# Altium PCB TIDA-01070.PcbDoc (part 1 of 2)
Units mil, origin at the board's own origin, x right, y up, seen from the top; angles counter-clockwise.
Board outline 4200 x 3450 mil, 4 copper layers (Top Layer, Signal Layer 1, Signal Layer 2, Bottom Layer), stack 61.668 mil thick; 155 components, 69 nets, 375 pads, 212 vias.
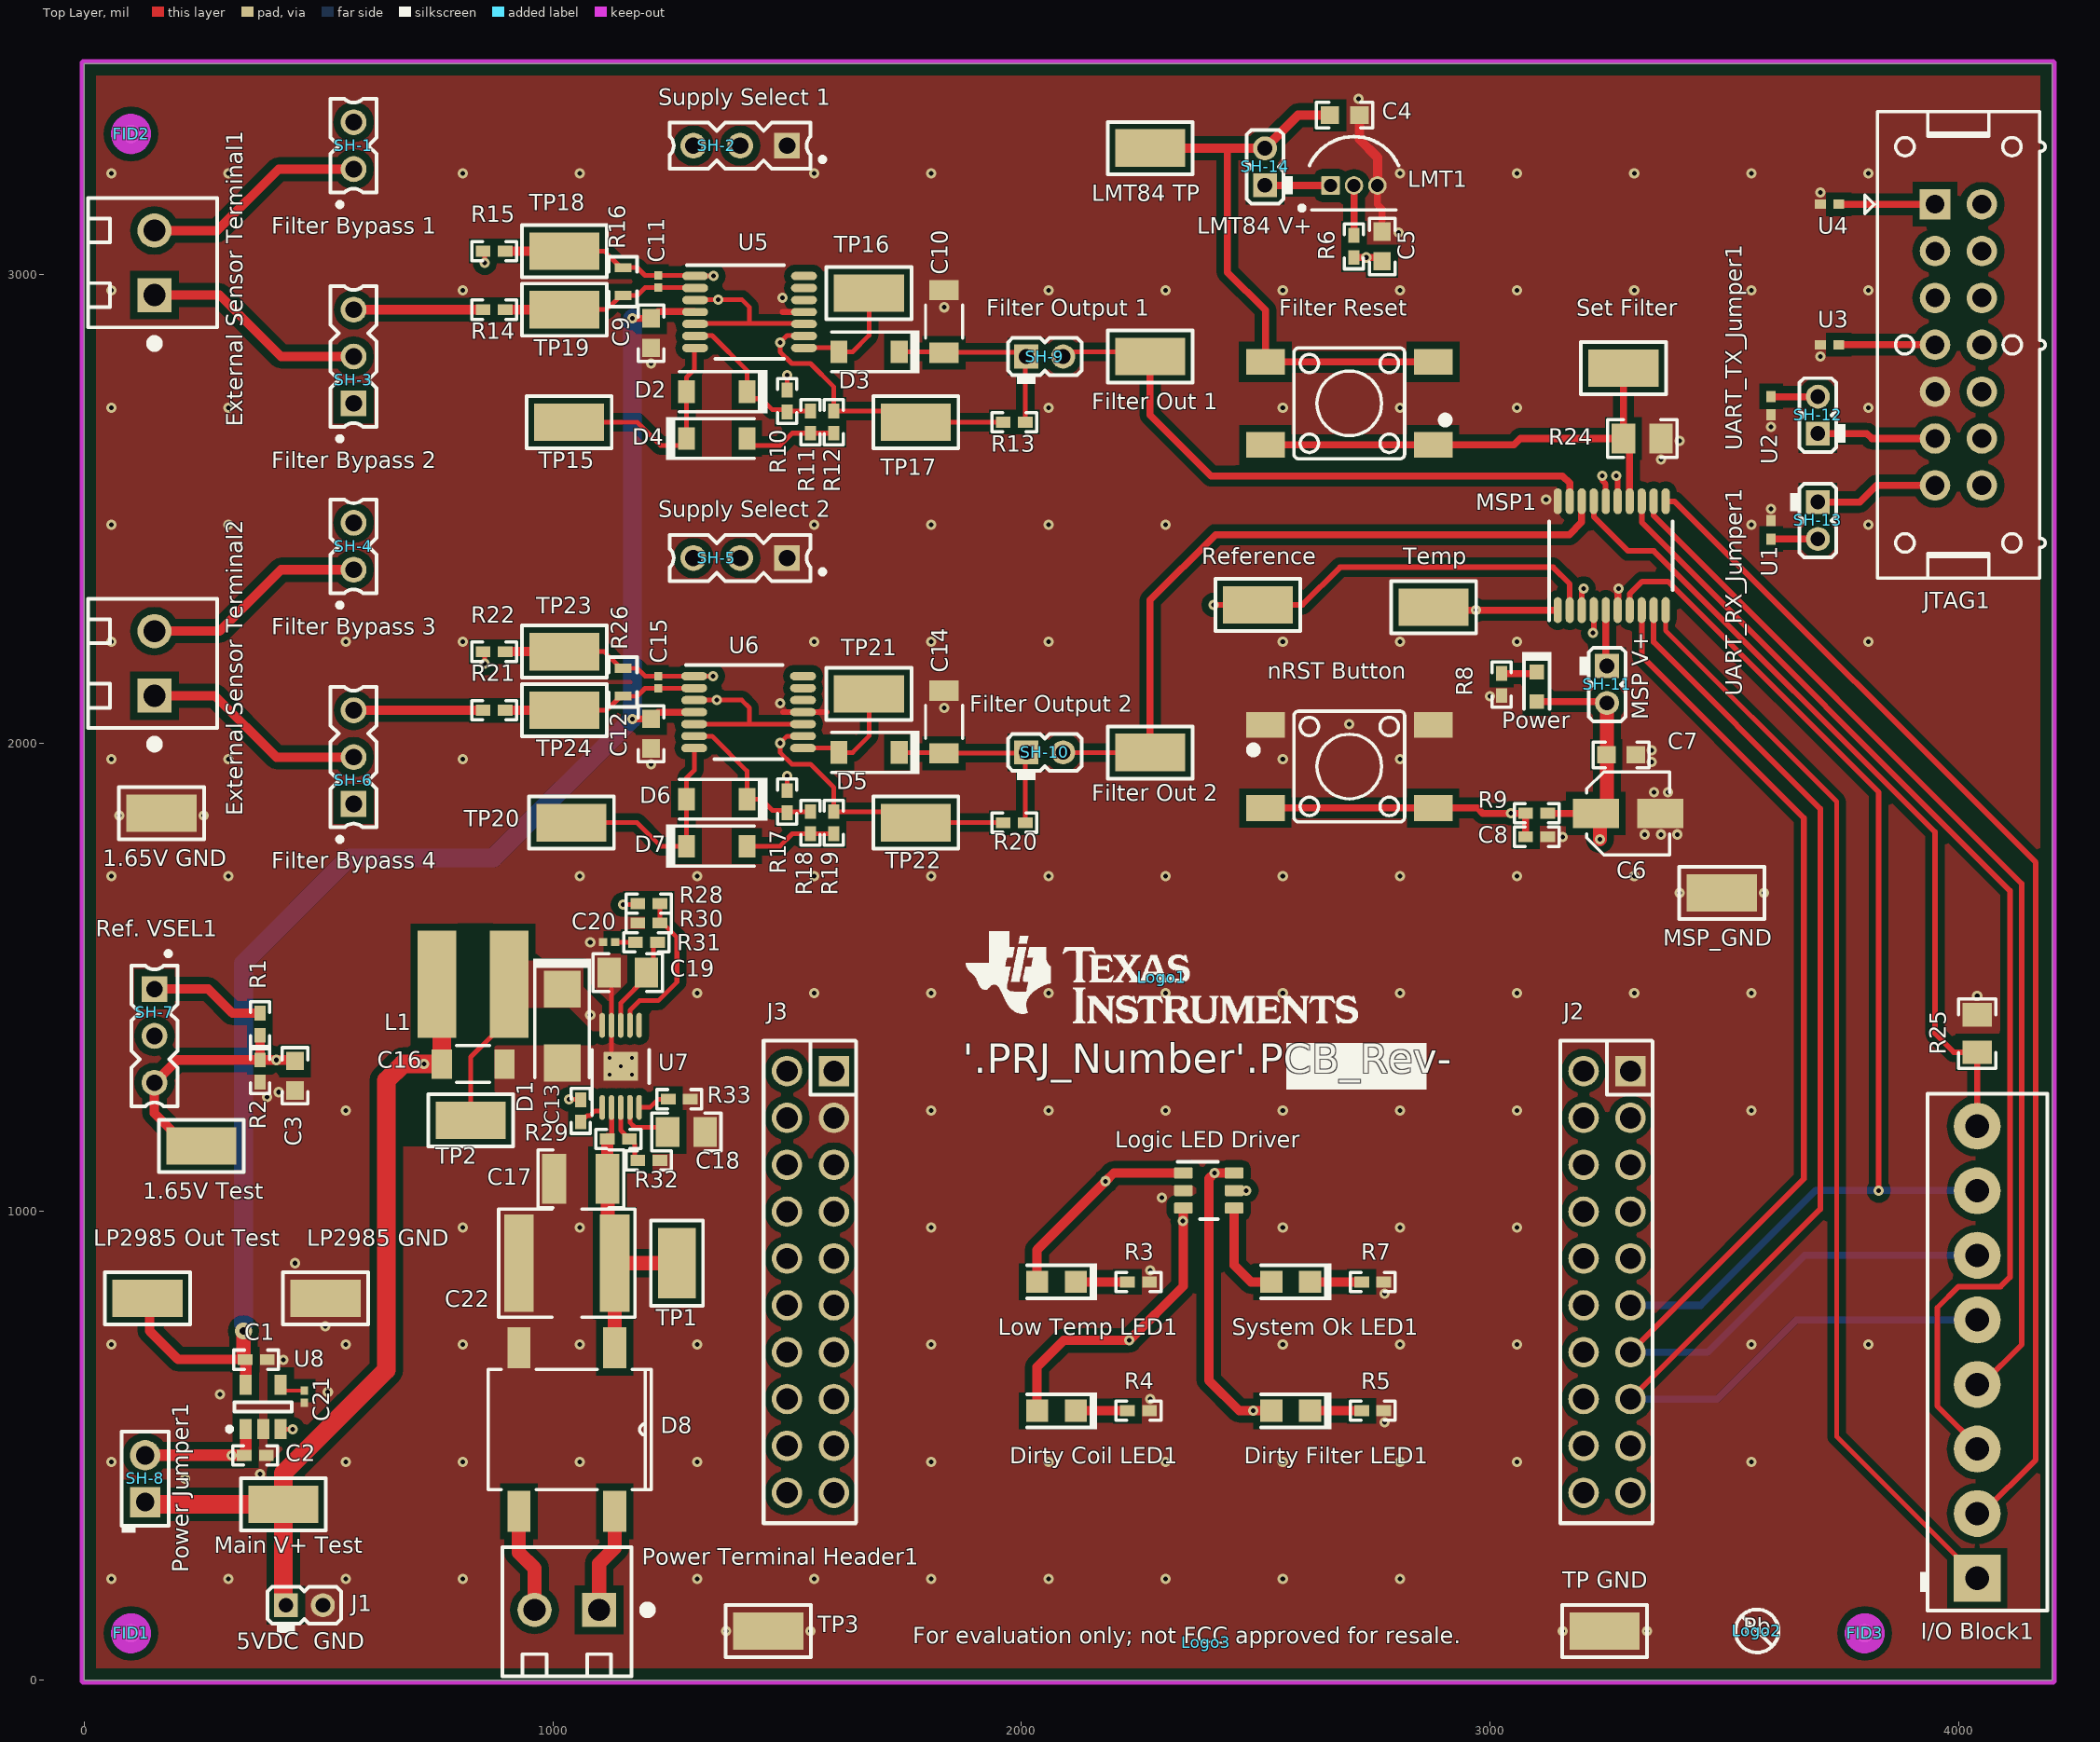
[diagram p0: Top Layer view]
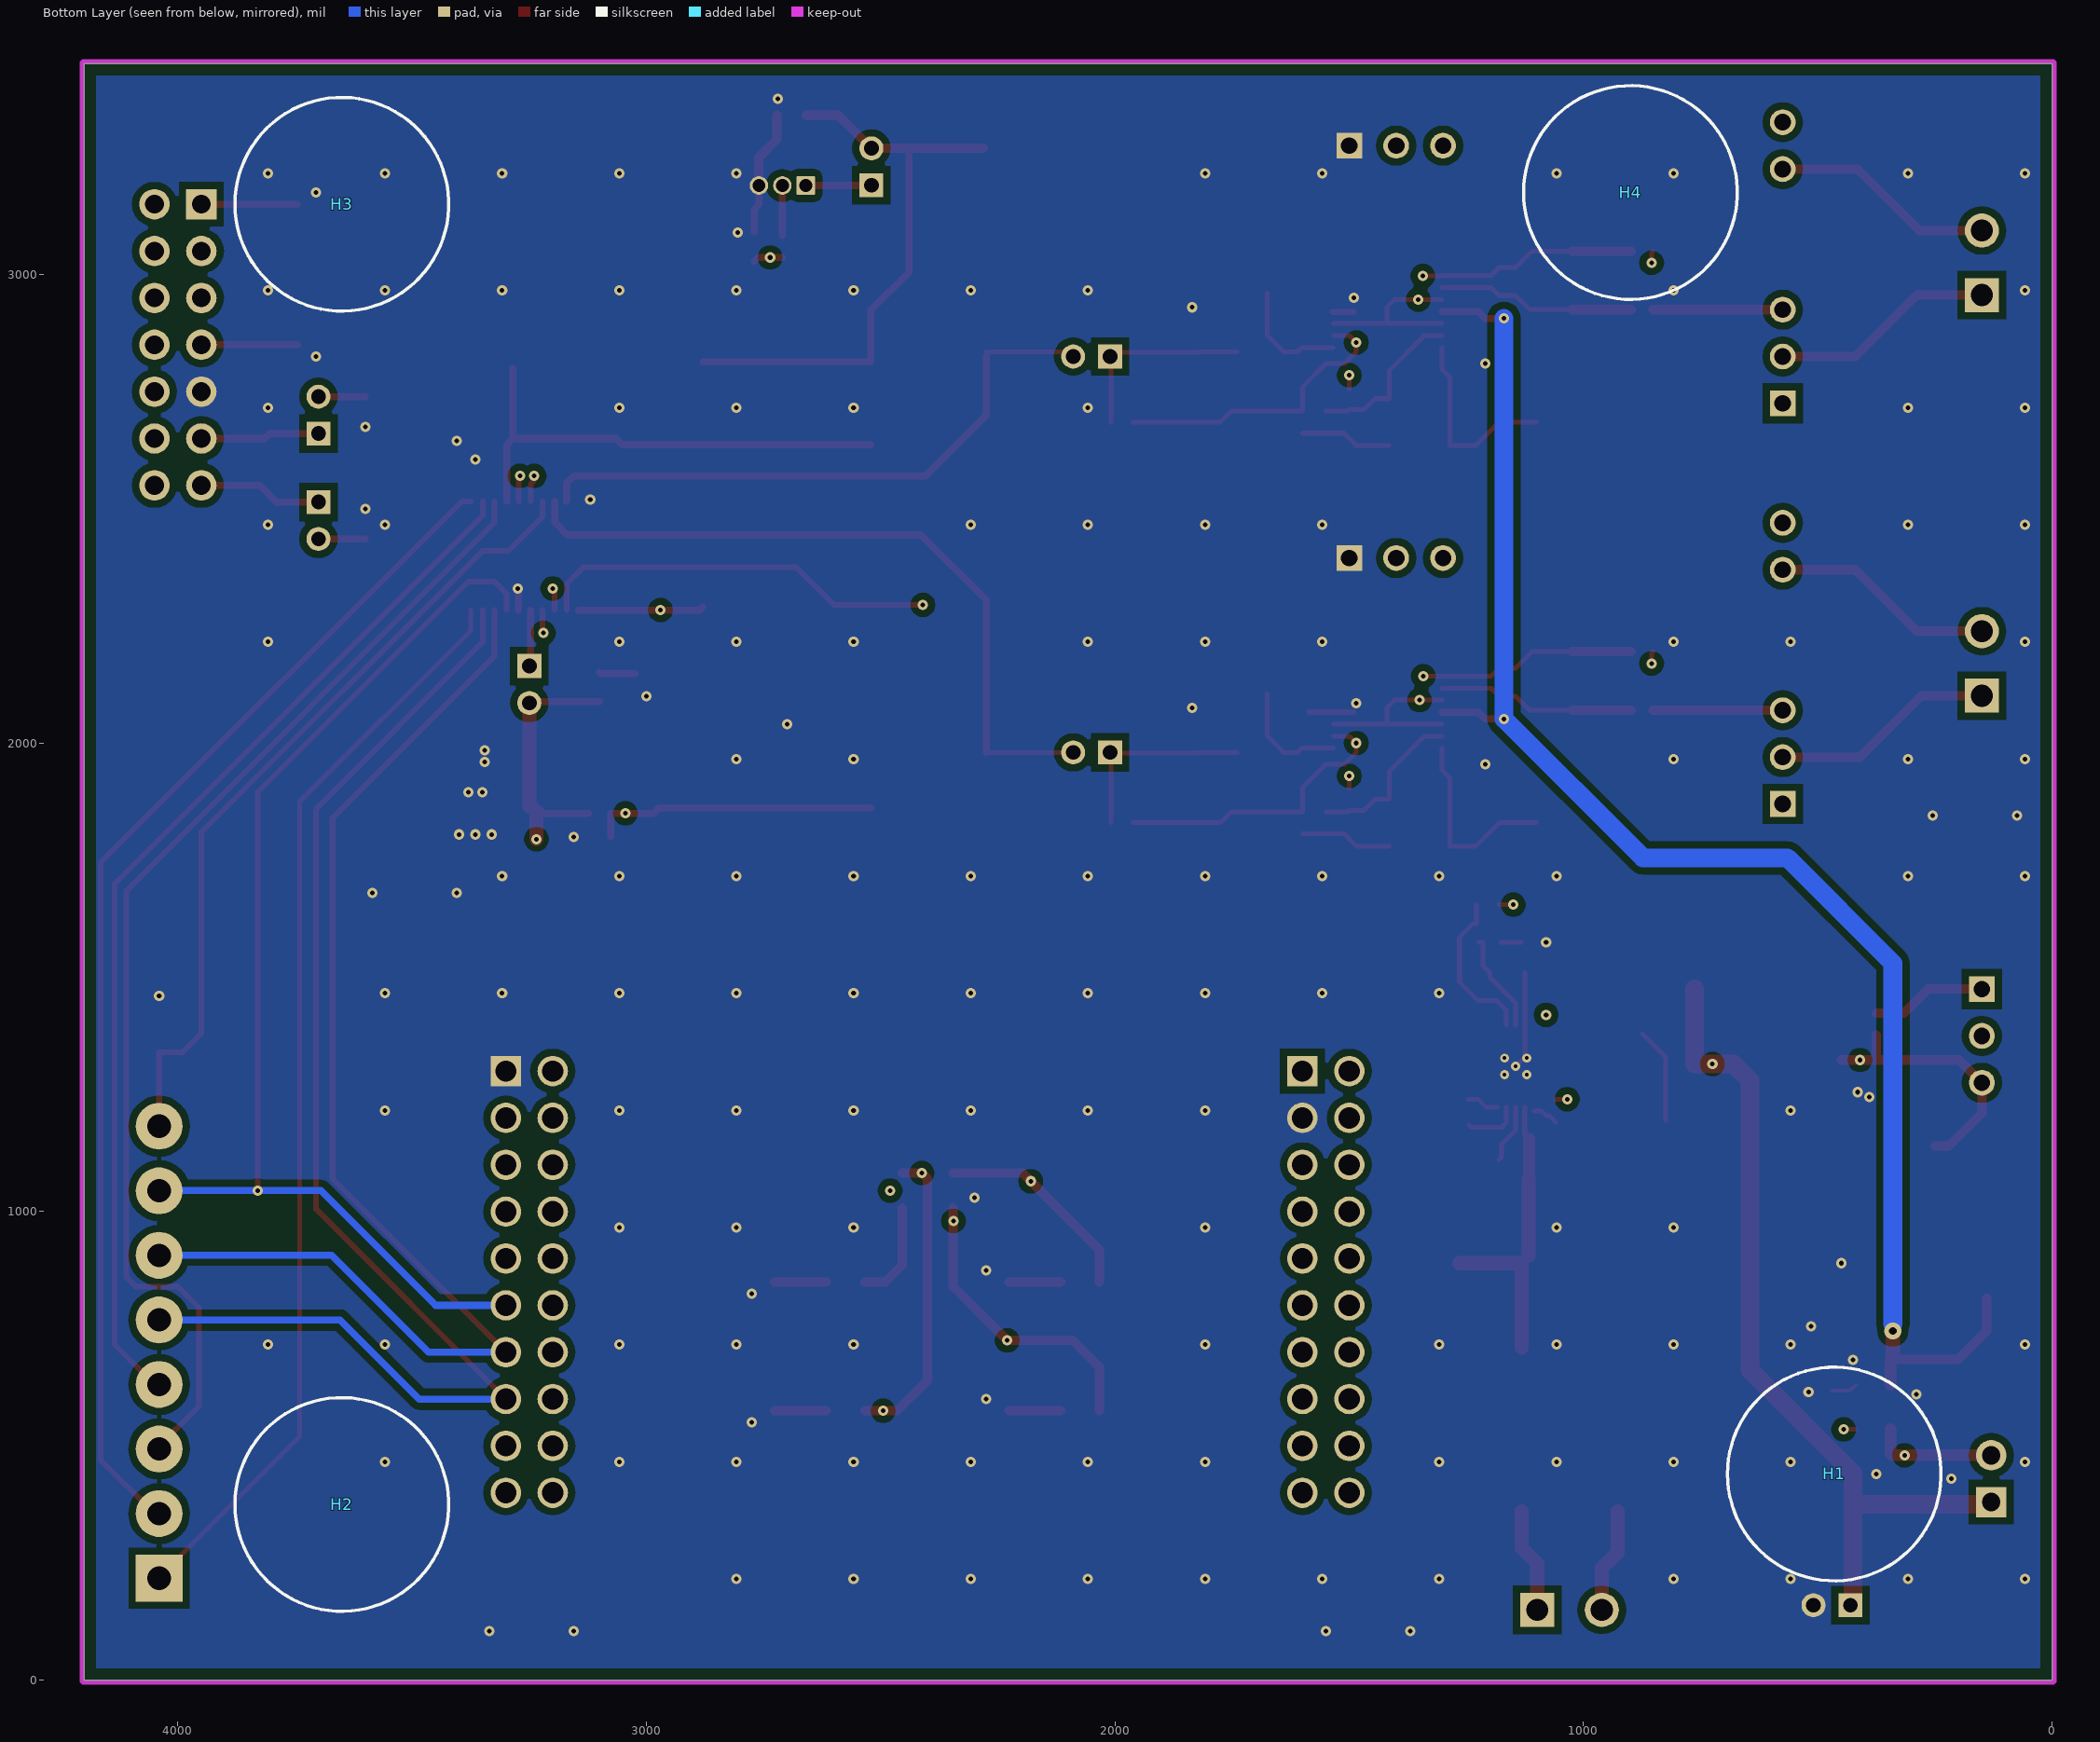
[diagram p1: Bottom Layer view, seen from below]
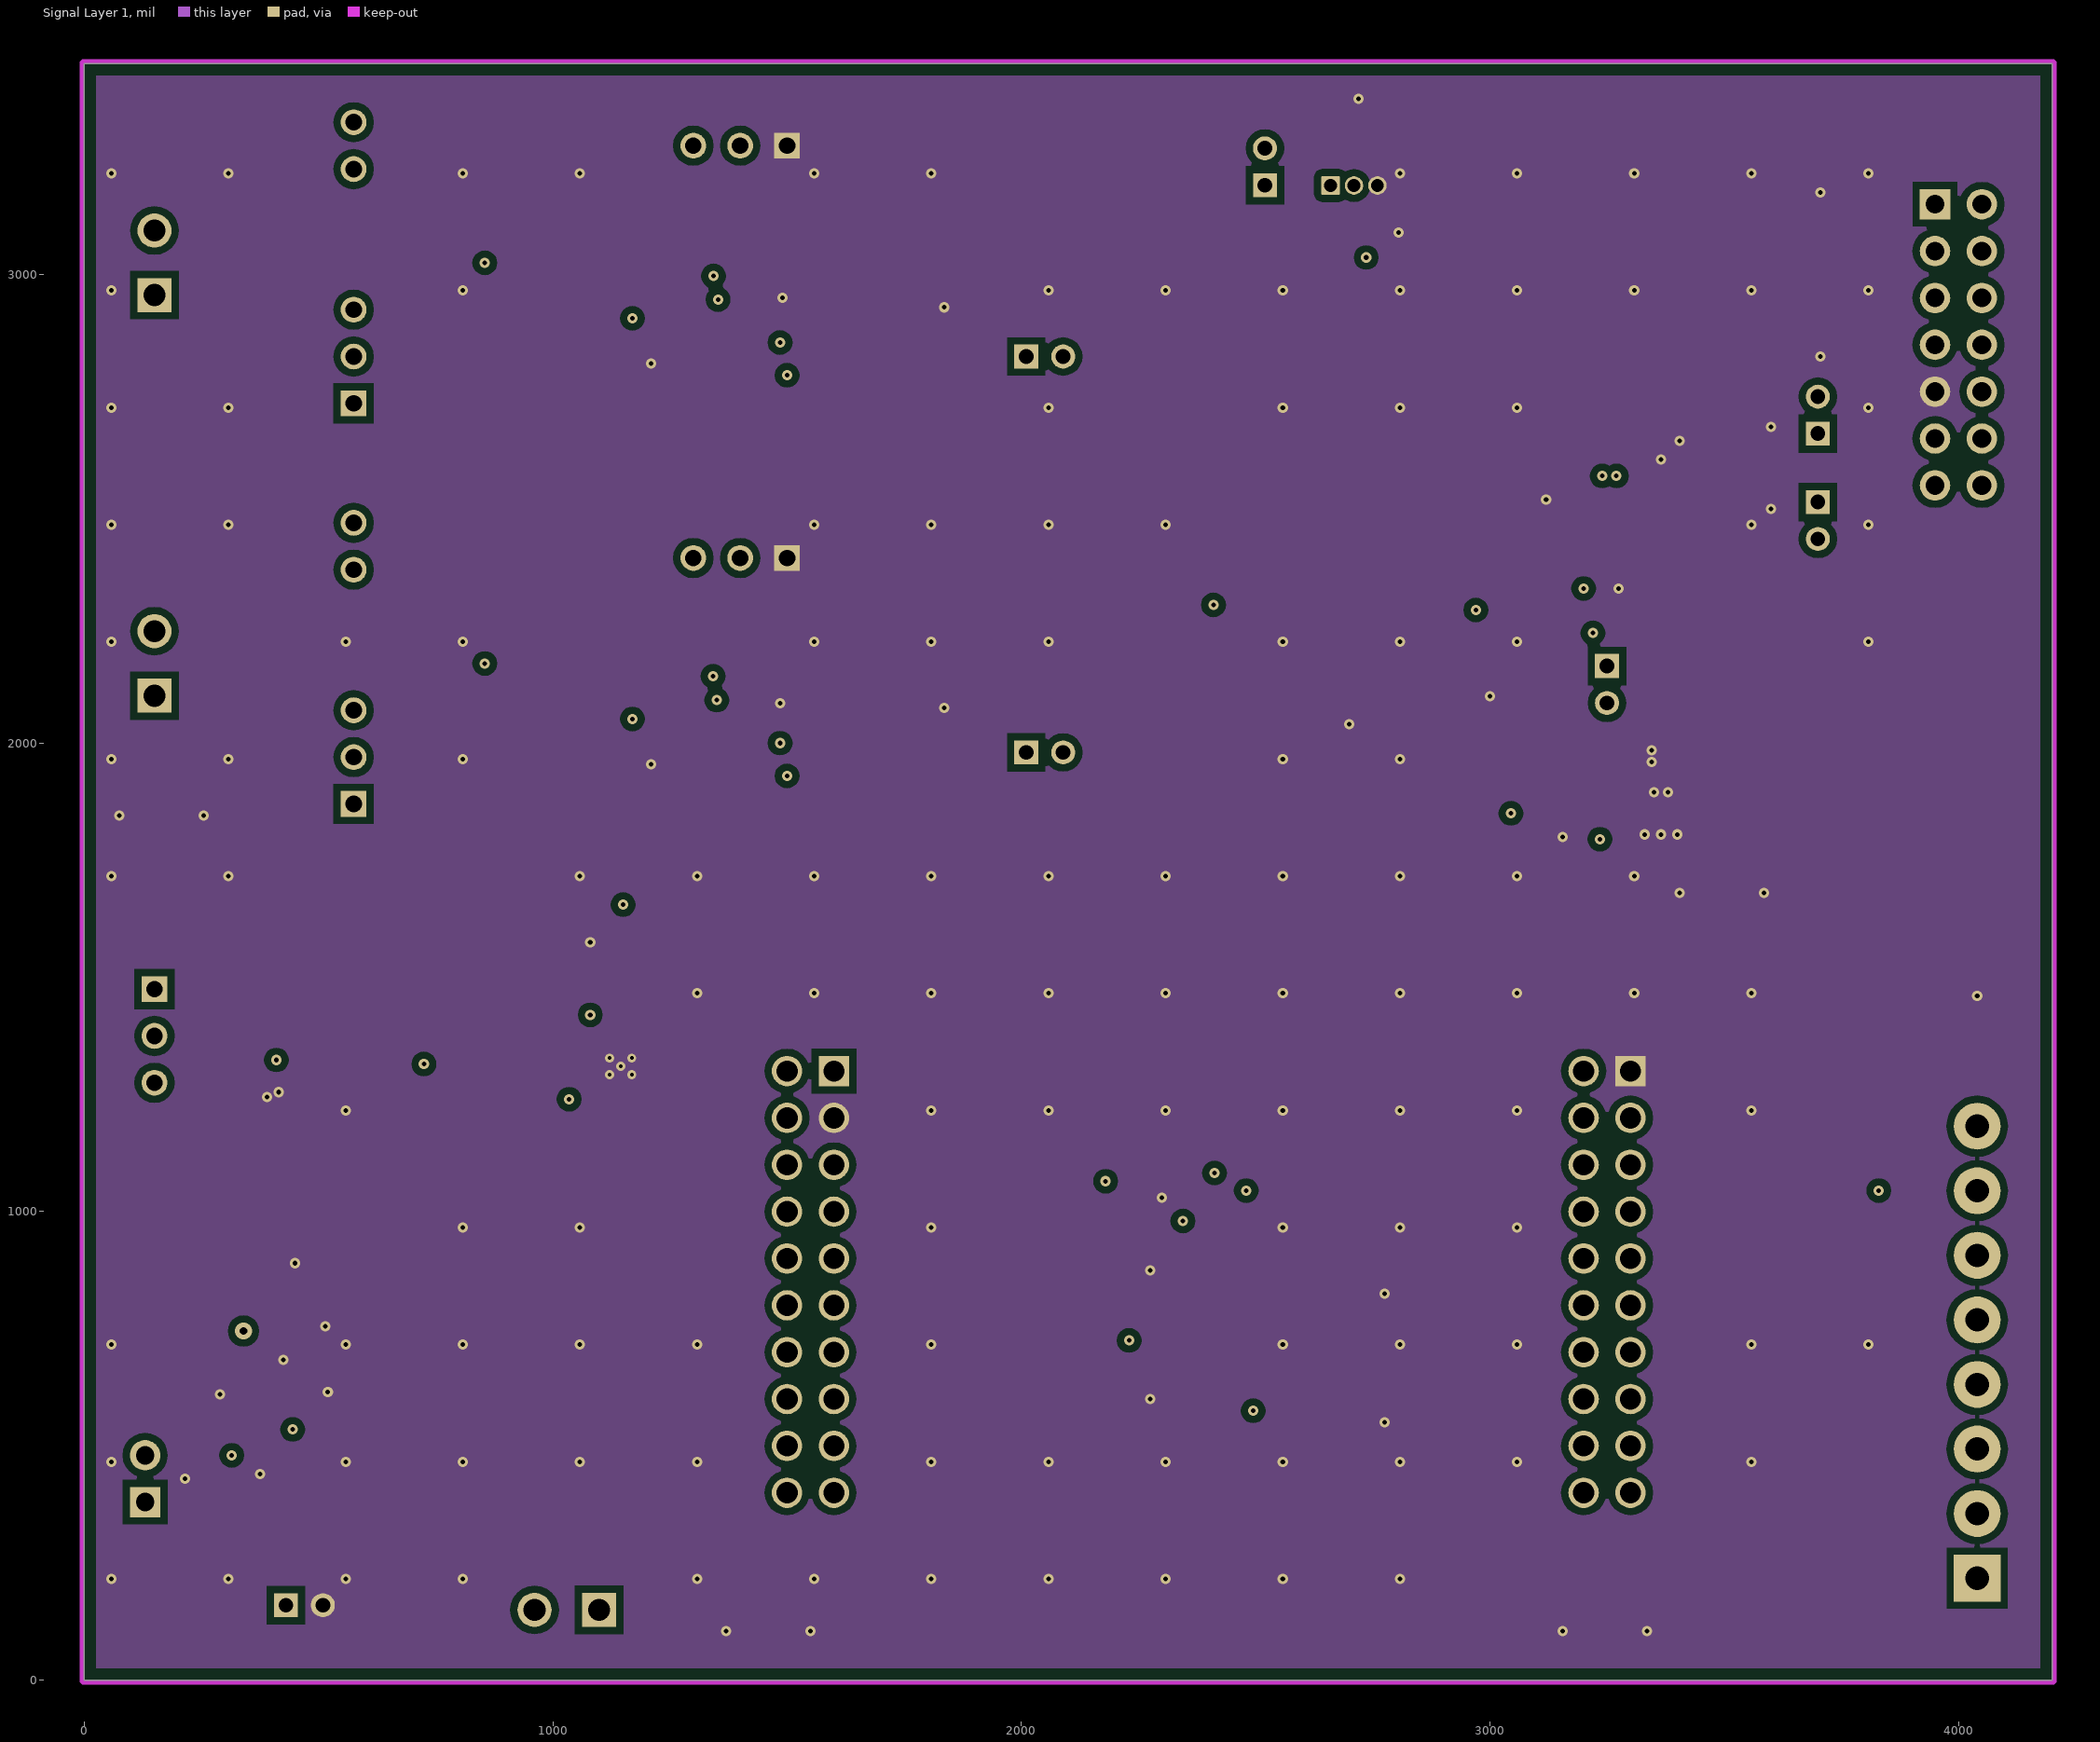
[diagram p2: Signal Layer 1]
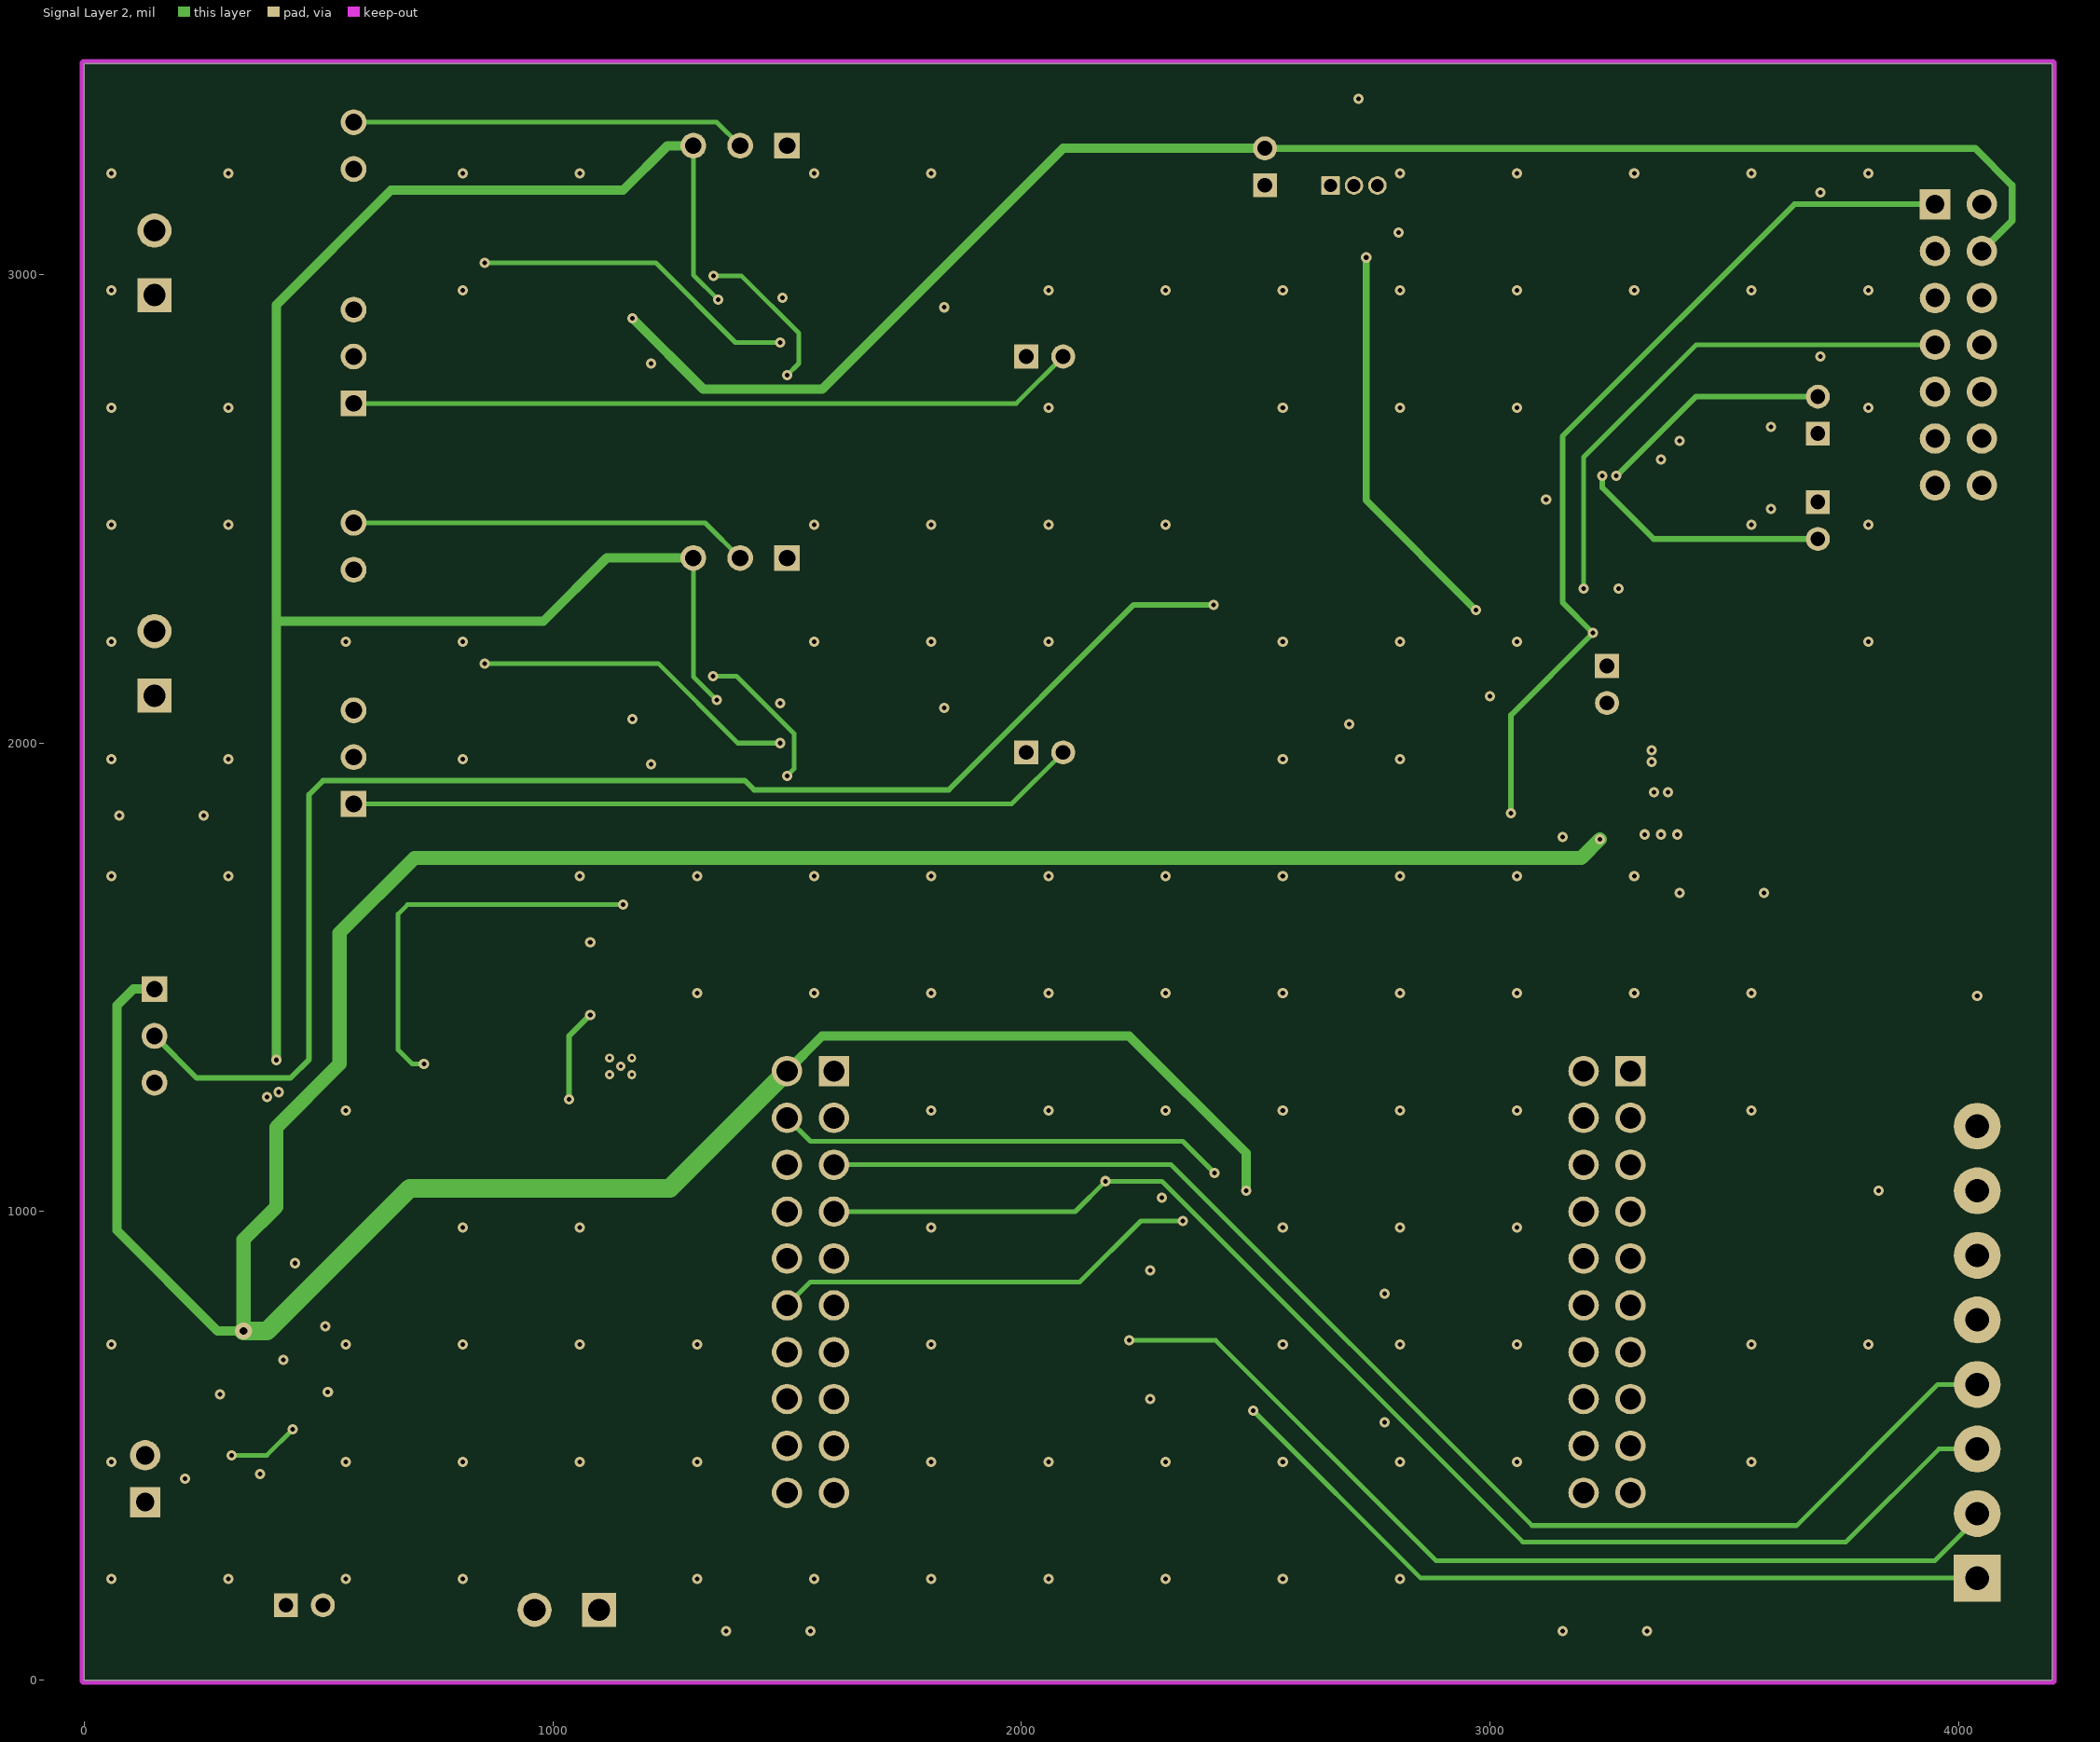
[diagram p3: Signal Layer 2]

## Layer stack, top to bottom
Top Solder: solder mask 0.4, Solder Resist, Dk 3.5
Top Layer: signal copper 1.417
Dielectric1: core 12, FR-4 High TG, Dk 4.3
Signal Layer 1: signal copper 1.417
Dielectric 2: prepreg 32, FR-4 High TG, Dk 4.3
Signal Layer 2: signal copper 1.417
Dielectric 3: core 12, FR-4 High TG, Dk 4.3
Bottom Layer: signal copper 1.417
Bottom Solder: solder mask 0.4, Solder Resist, Dk 3.5

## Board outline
0,0 0,3450 4200,3450 4200,0

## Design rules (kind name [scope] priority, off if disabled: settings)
AcuteAngle [All] p1: minimum=4.50000000000000E+0001 checktracksonly=FALSE
AssemblyTestPointUsage [All] p1: valid=2
BoardOutlineClearance BoardOutlineClearance_MountingHoles [OnCopper and InComponentClass('Mounting Holes')] p1: gap=40
BoardOutlineClearance BoardOutlineClearance_Poly [OnCopper and IsPoly] p2: gap=25
BoardOutlineClearance [OnCopper and Not InComponentClass('Logo') and not InComponentClass('FiducialMark') and not InRegion(1000,500,4000,800) and not InPoly] p3: gap=25
Clearance Clearance_Keepouts [((IsTrack Or IsArc) And Not InPoly) And IsFree and IsKeepOut vs ((IsTrack Or IsArc) And Not InPoly) And IsFree and IsKeepOut] p1: gap=0
Clearance Clearance_Poly [InPolygon] p2: gap=15
Clearance [All] p3: gap=7.87
ComponentClearance ComponentClearance_MountingHoles_FiducialMarks [InComponentClass('Mounting Holes') vs InComponentClass('FiducialMark')] p1: gap=50 collisioncheckmode=3 verticalgap=10 showdistances=FALSE
ComponentClearance ComponentClearance_Shunt [InComponentClass('Header') vs InComponentClass('Shunt')] p2: gap=0 collisioncheckmode=3 verticalgap=0 showdistances=FALSE
ComponentClearance ComponentClearance_Logo [InComponentClass('Logo')] p3: gap=0 collisioncheckmode=3 verticalgap=0 showdistances=FALSE
ComponentClearance ComponentClearance_ScrewToNut [(HasFootprint('NY PMS 440 0025 PH')) vs (HasFootprint('Keystone_1902C'))] p4: gap=5 collisioncheckmode=3 verticalgap=10 showdistances=FALSE
ComponentClearance ComponentClearance_MountingHoles [InComponentClass('Mounting Holes')] p5: gap=250 collisioncheckmode=3 verticalgap=100000 showdistances=FALSE
ComponentClearance ComponentClearance_SmallPassives [HasFootprint('0201*') or HasFootprint('0402*') or HasFootprint('0508') or HasFootprint('0603*') or HasFootprint('0612') or HasFootprint('0805*') or HasFootprint('0815*') or HasFootprint('0830*') or HasFootprint('1206*') or HasFootprint('1210*') or HasFootprint('1808*') or HasFootprint('1812*') or HasFootprint('1825*') or HasFootprint('2010*') or HasFootprint('2220*') or HasFootprint('2225*') or HasFootprint('2512*') or HasFootprint('2728*') or HasFootprint('3518*') vs HasFootprint('0201*') or HasFootprint('0402*') or HasFootprint('0508') or HasFootprint('0603*') or HasFootprint('0612') or HasFootprint('0805*') or HasFootprint('0815*') or HasFootprint('0830*') or HasFootprint('1206*') or HasFootprint('1210*') or HasFootprint('1808*') or HasFootprint('1812*') or HasFootprint('1825*') or HasFootprint('2010*') or HasFootprint('2220*') or HasFootprint('2225*') or HasFootprint('2512*') or HasFootprint('2728*') or HasFootprint('3518*')] p6: gap=10 collisioncheckmode=3 verticalgap=10 showdistances=FALSE
ComponentClearance ComponentClearance_THtoSMT [IsThruComponent vs IsSMTComponent] p7: gap=30 collisioncheckmode=3 verticalgap=30 showdistances=FALSE
ComponentClearance ComponentClearance_THtoTH [IsThruComponent vs IsThruComponent] p8: gap=30 collisioncheckmode=3 verticalgap=30 showdistances=FALSE
ComponentClearance [All] p9: gap=10 collisioncheckmode=3 verticalgap=10 showdistances=FALSE
DiffPairsRouting [All] p1: maxlimit=100 minlimit=10 mostfreqgap=10 toplayer_minwidth=15 toplayer_maxwidth=15 toplayer_prefwidth=15 midlayer1_minwidth=15 midlayer1_maxwidth=15 midlayer1_prefwidth=15 midlayer2_minwidth=15 midlayer2_maxwidth=15 midlayer2_prefwidth=15 bottomlayer_minwidth=15 bottomlayer_maxwidth=15 bottomlayer_prefwidth=15 maxuncoupledlength=1000
FabricationTestPointUsage TestPointUsage [All] p1: valid=2 allowmultiple=FALSE
FabricationTestpoint Testpoint [All] p1: side=3 testpointundercomponent=TRUE minsize=40 maxsize=100 preferedsize=60 minholesize=0 maxholesize=40 preferedholesize=32 testpointgrid=1 allowsidetop=TRUE allowsidebottom=TRUE usegrid=TRUE gridtolerance=0.01
FanoutControl Fanout_LCC [IsLCC] p1: bgadir=Out bgaviamode=Centered fanoutstyle=Auto fanoutdirection=Alternating viagrid=1 // Fanout_LCC (Default Rule)
FanoutControl Fanout_BGA [IsBGA] p2: bgadir=Out bgaviamode=Centered fanoutstyle=Auto fanoutdirection=Alternating viagrid=1 // Fanout_BGA (Default Rule)
FanoutControl Fanout_Default [All] p4: bgadir=Out bgaviamode=Centered fanoutstyle=Auto fanoutdirection=Alternating viagrid=1 // Fanout_Default (Default Rule)
FanoutControl Fanout_Small [(CompPinCount < 5)] p5: bgadir=Out bgaviamode=Centered fanoutstyle=Auto fanoutdirection=OutThenIn viagrid=1 // Fanout_Small (Default Rule)
HoleSize [All] p1: absolutevalues=TRUE maxlimit=251 minlimit=7.87 maxpercent=80.000 minpercent=20.000
MinimumAnnularRing MinimumAnnularRing_ThermalPadVias [IsVia and InAnyComponent] p1: minimumring=5.91
MinimumAnnularRing [All] p2: minimumring=5.9
MinimumSolderMaskSliver MinimumSolderMaskSliver_Logo [InComponentClass('Logo') vs InComponentClass('Logo')] p1: minsoldermaskwidth=0.7
MinimumSolderMaskSliver [All] p2: minsoldermaskwidth=3.94
PlaneConnect [All] p1: planeconnectstyle=Relief reliefexpansion=10 reliefentries=4 reliefconductorwidth=10 reliefairgap=10
PolygonConnect [All] p1: connectstyle=Direct reliefconductorwidth=10 reliefentries=4 polygonreliefangle="90 Angle" airgapwidth=10
RoutingVias ThermalPadVias [IsVia and InAnyComponent] p1: holewidth=7.87 width=19.68 viastyle="Through Hole" minholewidth=7.87 minwidth=19.68 maxholewidth=12.99 maxwidth=23.62
RoutingVias [All] p2: holewidth=10 width=26 viastyle="Through Hole" minholewidth=7.87 minwidth=22 maxholewidth=40 maxwidth=65
SilkToBoardRegionClearance [Not ((IsComment or IsDesignator) And (Hide <> 'False')) and not InRegion(1000,500,4000,800)] p1:
SilkToSilkClearance SilkToSilkClearance_Pb-FreeLogo [(HasFootprint('Pb-Free_Overlay_Medium') OR HasFootprint('Pb-Free_Overlay_Small')) vs (HasFootprint('Pb-Free_Overlay_Medium') OR HasFootprint('Pb-Free_Overlay_Small'))] p1: silktosilkclearance=0
SilkToSilkClearance [All] p2: silktosilkclearance=4
SilkToSolderMaskClearance SilkToComponentPadClearance [IsPad and InAnycomponent] p1: minsilkscreentomaskgap=5 clearancetoexposedcopper=TRUE
SilkToSolderMaskClearance "Silk to Solder Mask Opening" [All] p2: minsilkscreentomaskgap=4 clearancetoexposedcopper=FALSE
SolderMaskExpansion [All] p1: expansion=1.97
Width [All] p1: maxlimit=100 minlimit=7.8 preferedwidth=10 midlayer1_minwidth=10 midlayer2_minwidth=10 bottomlayer_minwidth=10 minimp=50.000000 maximp=50.000000 favimp=50.000000 checkconnectedcopper=TRUE
15 further rules are at their usual default settings.

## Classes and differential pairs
component class "Ac to DC Converter": C13 C16 C17 C18 C19 C20 C22 D1 D8 L1 "Power Terminal Header1" R28 R29 R30 R31 R32 R33 TP1 TP2 TP3 U7
component class Shunt: SH-1 SH-2 SH-3 SH-4 SH-5 SH-6 SH-7 SH-8 SH-9 SH-10 SH-11 SH-12 SH-13 SH-14
component class Board_IO_Interface: "1.65V GND" "1.65V Test" C1 C2 C3 C21 "External Sensor Terminal1" "External Sensor Terminal2" "I/O Block1" J1 J2 J3 JTAG1 "LP2985 GND" "LP2985 Out Test" "Main V+ Test" "Power Jumper1" R1 R2 "Ref. VSEL1" U1 U2 U3 U4 U8 UART_RX_Jumper1 UART_TX_Jumper1
component class Sensor_Filtering: C9 C10 C11 C12 C14 C15 D2 D3 D4 D5 D6 D7 "Filter Bypass 1" "Filter Bypass 2" "Filter Bypass 3" "Filter Bypass 4" "Filter Output 1" "Filter Output 2" R10 R11 R12 R13 R14 R15 R16 R17 R18 R19 R20 R21 R22 R26 "Supply Select 1" "Supply Select 2" TP15 TP16 TP17 TP18 TP19 TP20 TP21 TP22 TP23 TP24 U5 U6
component class Internal_Processing: C4 C5 C6 C7 C8 "Dirty Coil LED1" "Dirty Filter LED1" "Filter Out 1" "Filter Out 2" "Filter Reset" LMT1 "LMT84 TP" "LMT84 V+" "Logic LED Driver" "Low Temp LED1" MSP1 "MSP V+" MSP_GND "nRST Button" Power R3 R4 R5 R6 R7 R8 R9 R24 R25 Reference "Set Filter" "System Ok LED1" Temp TP7 "TP GND"
component class Header: "Filter Bypass 1" "Filter Bypass 2" "Filter Bypass 3" "Filter Bypass 4" "Filter Output 1" "Filter Output 2" J1 "LMT84 V+" "MSP V+" "Power Jumper1" "Ref. VSEL1" "Supply Select 1" "Supply Select 2" UART_RX_Jumper1 UART_TX_Jumper1
component class AssemblyNote: ZZ2 ZZ3 ZZ4
component class FiducialMark: FID1 FID2 FID3
component class Logo: Logo1
component class TIDA-01070__EVM_Hardware: !PCB FID1 FID2 FID3 H1 H2 H3 H4 Logo1 Logo2 Logo3 SH-1 SH-2 SH-3 SH-4 SH-5 SH-6 SH-7 SH-8 SH-9 SH-10 SH-11 SH-12 SH-13 SH-14 ZZ2 ZZ3 ZZ4

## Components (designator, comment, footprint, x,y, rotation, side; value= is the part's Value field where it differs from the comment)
"1.65V GND" "TESTPOINT" Keystone_5019 165,1850 r180 top
"1.65V Test" "TESTPOINT" Keystone_5019 250,1140 r180 top
C1 "GRM155C80J225KE95D" 0402 367,684 r0 top
C2 "GRM155R60J105KE19D" 0402 365,480 r0 top
C3 "0603YC104JAT2A" 0603 450,1290 r90 top
C4 "0603YC104JAT2A" 0603 2690,3340 r180 top
C5 "0603YC104JAT2A" 0603 2770,3060 r270 top
C6 "EEE-FK1E100R" SM_RADIAL_B 3295,1850 r0 top
C7 "0603YC104JAT2A" 0603 3280,1975 r180 top
C8 "GRM155R71C102KA01D" 0402 3100,1800 r180 top
C9 "0603YC104JAT2A" 0603 1210,2875 r90 top
C10 "GRM31CR70J226KE19L" 1206_180 1835,2900 r90 top
C11 "GRM033R71C681KA01D" 0201 1225,2985 r270 top
C12 "0603YC104JAT2A" 0603 1210,2020 r90 top
C13 "GRM155R61A104KA01D" 0402 1060,1215 r90 top
C14 "GRM31CR70J226KE19L" 1206_180 1835,2045 r90 top
C15 "GRM033R71C681KA01D" 0201 1225,2130 r270 top
C16 "GRM31CR61A476KE15L" 1206_180 830,1315 r0 top
C17 "GRM32ER72A225KA35L" 1210_270 1060,1070 r180 top
C18 "CC0805KRX7R9BB682" 0805_HV 1285,1170 r0 top
C19 "GQM2195C2A9R0CB01D" 0805_HV 1160,1510 r180 top
C20 "GRM033C80J123KE01D" 0201 1120,1575 r180 top
C21 "GRM033R60J103KA01D" 0201 470,605 r270 top
C22 "22201C106MAT2A" 2220_280 1030,890 r180 top
D1 "B160-13-F" SMA 1020,1396 r270 top
D2 "1N4148W-7-F" SOD-123 1350,2750 r180 top
D3 "1N4148W-7-F" SOD-123 1675,2835 r180 top
D4 "1N4148W-7-F" SOD-123 1350,2650 r0 top
D5 "1N4148W-7-F" SOD-123 1675,1980 r180 top
D6 "1N4148W-7-F" SOD-123 1350,1880 r180 top
D7 "1N4148W-7-F" SOD-123 1350,1780 r0 top
D8 "DF02S-E3/77" DF-S 1030,535 r270 top
"Dirty Coil LED1" "LTST-C170KRKT" LED_LTST-C170_Red 2075,575 r0 top
"Dirty Filter LED1" "LTST-C170KSKT" LED_LTST-C170 2575,575 r0 top
"External Sensor Terminal1" "OSTTE020161" On-Shore_OSTTE020161 150,3025 r90 top
"External Sensor Terminal2" "OSTTE020161" On-Shore_OSTTE020161 150,2170 r90 top
FID1 "Fiducial" Fiducial10-20 100,100 r90 top
FID2 "Fiducial" Fiducial10-20 100,3300 r90 top
FID3 "Fiducial" Fiducial10-20 3800,100 r90 top
"Filter Bypass 1" "SL 11 112 02G" Fischer_SL-11-112-02G 575,3275 r90 top
"Filter Bypass 2" "SL 11 112 03G" Fischer_SL-11-112-03G 575,2825 r90 top
"Filter Bypass 3" "SL 11 112 02G" Fischer_SL-11-112-02G 575,2420 r90 top
"Filter Bypass 4" "SL 11 112 03G" Fischer_SL-11-112-03G 575,1970 r90 top
"Filter Out 1" "TESTPOINT" Keystone_5019 2275,2825 r0 top
"Filter Out 2" "TESTPOINT" Keystone_5019 2275,1980 r180 top
"Filter Output 1" "M22-2510205" Harwin_M22-2510205 2050,2825 r0 top
"Filter Output 2" "M22-2510205" Harwin_M22-2510205 2050,1980 r0 top
"Filter Reset" "4-1437565-1" SW_FSM4JSMA 2700,2725 r270 top
H1 "SJ-5303 (CLEAR)" Bumpon_SJ5003Transparent 465,440 r180 bottom
H2 "SJ-5303 (CLEAR)" Bumpon_SJ5003Transparent 3650,375 r180 bottom
H3 "SJ-5303 (CLEAR)" Bumpon_SJ5003Transparent 3650,3150 r180 bottom
H4 "SJ-5303 (CLEAR)" Bumpon_SJ5003Transparent 900,3175 r180 bottom
"I/O Block1" "ED555/8DS" On-Shore_ED555_8DS 4040,700 r90 top
J1 "M22-2510205" Harwin_M22-2510205 470,160 r0 top
J2 "SSW-110-23-F-D" CONN_SSW-110-23-F-D 3250,850 r90 top
J3 "SSW-110-23-F-D" CONN_SSW-110-23-F-D 1550,850 r90 top
JTAG1 "SBH11-PBPC-D07-ST-BK" CONN_SBH11-PBPC-D07-ST-BK 4000,2850 r270 top
L1 "SDR0604-331KL" SDR0604 830,1485 r180 top
LMT1 "LMT84LPM" LP0003A_straight 2710,3190 r90 top
"LMT84 TP" "TESTPOINT" Keystone_5019 2275,3270 r180 top
"LMT84 V+" "M22-2510205" Harwin_M22-2510205 2520,3230 r90 top
"Logic LED Driver" "SN74LVC1G27DBVR" DBV0006A_N 2400,1045 r0 top
Logo1 "Texas Instruments" TI_Stacked_Overlay_Small 2300,1500 r0 top
Logo2 "Pb-Free Symbol" Pb-Free_Overlay_Small 3570,105 r0 top
Logo3 "FCC disclaimer" FCC_disclaimer 2395,80 r0 top
"Low Temp LED1" "LTST-C170KFKT" LTST-C170KFKT_Orange 2075,850 r0 top
"LP2985 GND" "TESTPOINT" Keystone_5019 515,815 r0 top
"LP2985 Out Test" "TESTPOINT" Keystone_5019 135,815 r0 top
"Main V+ Test" "TESTPOINT" Keystone_5019 425,375 r0 top
MSP1 "MSP430FR2311IPW20R" PW0020A_N 3260,2400 r90 top locked
"MSP V+" "M22-2510205" Harwin_M22-2510205 3250,2125 r270 top
MSP_GND "TESTPOINT" Keystone_5019 3495,1680 r180 top
"nRST Button" "4-1437565-1" SW_FSM4JSMA 2700,1950 r90 top
Power "150060BS75000" WL-SMCW_Blue 3100,2120 r270 top
"Power Jumper1" "PartNumber" TE_5-146278-2 130,430 r90 top
"Power Terminal Header1" "" On-Shore_OSTTE020161 1030,150 r180 top
R1 "CRCW040210K0FKED" 0402 375,1400 r90 top
R2 "CRCW040210K0FKED" 0402 375,1300 r270 top
R3 "CRCW0402270RJNED" 0402 2250,850 r0 top
R4 "CRCW0402270RJNED" 0402 2250,575 r0 top
R5 "CRCW0402270RJNED" 0402 2750,575 r0 top
R6 "CRCW04021K50FKED" 0402 2710,3060 r270 top
R7 "CRCW0402270RJNED" 0402 2750,850 r0 top
R8 "CRCW0402270RJNED" 0402 3025,2125 r270 top
R9 "CRCW040247K0JNED" 0402 3100,1850 r0 top
R10 "RG1005P-104-B-T5" 0402 1500,2730 r270 top
R11 "RG1005P-104-B-T5" 0402 1550,2685 r270 top
R12 "CRCW040251K1FKED" 0402 1600,2685 r90 top
R13 "RG1005P-104-B-T5" 0402 1985,2685 r0 top
R14 "CRCW040210K0FKED" 0402 875,2925 r0 top
R15 "RG1005P-104-B-T5" 0402 875,3050 r180 top
R16 "CRCW0603200MJPEAHR" 0603_HR 1150,2985 r90 top
R17 "RG1005P-104-B-T5" 0402 1500,1875 r270 top
R18 "RG1005P-104-B-T5" 0402 1550,1830 r270 top
R19 "CRCW040251K1FKED" 0402 1600,1830 r90 top
R20 "RG1005P-104-B-T5" 0402 1985,1830 r0 top
R21 "CRCW040210K0FKED" 0402 875,2070 r180 top
R22 "RG1005P-104-B-T5" 0402 875,2195 r180 top
R24 "RG2012P-473-B-T5" 0805_HV 3325,2650 r180 top
R25 "RG2012P-473-B-T5" 0805_HV 4040,1380 r270 top
R26 "CRCW0603200MJPEAHR" 0603_HR 1150,2130 r90 top
R28 "CRCW040253K6FKED" 0402 1205,1657 r180 top
R29 "CRCW0402105KFKED" 0402 1140,1155 r180 top
R30 "CRCW040210K0FKED" 0402 1205,1616 r0 top
R31 "CRCW040271K5FKED" 0402 1200,1575 r0 top
R32 "CRCW04026K49FKED" 0402 1205,1109 r180 top
R33 "CRCW0402402KFKED" 0402 1270,1240 r180 top
"Ref. VSEL1" "SL 11 112 03G" Fischer_SL-11-112-03G 150,1375 r270 top
Reference "TESTPOINT" Keystone_5019 2505,2295 r180 top
"Set Filter" "TESTPOINT" Keystone_5019 3285,2800 r180 top
SH-1 "969102-0000-DA" SNT-100-BK-G 575,3275 r90 top
SH-2 "969102-0000-DA" SNT-100-BK-G 1350,3275 r0 top
SH-3 "969102-0000-DA" SNT-100-BK-G 575,2775 r90 top
SH-4 "969102-0000-DA" SNT-100-BK-G 575,2420 r90 top
SH-5 "969102-0000-DA" SNT-100-BK-G 1350,2395 r0 top
SH-6 "969102-0000-DA" SNT-100-BK-G 575,1920 r90 top
SH-7 "969102-0000-DA" SNT-100-BK-G 150,1425 r90 top
SH-8 "969102-0000-DA" SNT-100-BK-G 130,430 r270 top
SH-9 "2SN-BK-G" 2SN-BK-G 2050,2825 r0 top
SH-10 "2SN-BK-G" 2SN-BK-G 2050,1980 r0 top
SH-11 "2SN-BK-G" 2SN-BK-G 3250,2125 r90 top
SH-12 "2SN-BK-G" 2SN-BK-G 3700,2700 r90 top
SH-13 "2SN-BK-G" 2SN-BK-G 3700,2475 r90 top
SH-14 "2SN-BK-G" 2SN-BK-G 2520,3230 r90 top
"Supply Select 1" "SL 11 112 03G" Fischer_SL-11-112-03G 1400,3275 r180 top
"Supply Select 2" "SL 11 112 03G" Fischer_SL-11-112-03G 1400,2395 r180 top
"System Ok LED1" "LTST-C170KGKT" LTST-C170KGKT_Green 2575,850 r0 top
Temp "TESTPOINT" Keystone_5019 2880,2290 r180 top
TP1 "TESTPOINT" Keystone_5019 1265,890 r90 top
TP2 "TESTPOINT" Keystone_5019 825,1195 r180 top
TP3 "TESTPOINT" Keystone_5019 1460,105 r0 top
TP15 "TESTPOINT" Keystone_5019 1035,2685 r0 top
TP16 "TESTPOINT" Keystone_5019 1675,2960 r180 top
TP17 "TESTPOINT" Keystone_5019 1775,2685 r180 top
TP18 "TESTPOINT" Keystone_5019 1025,3050 r180 top
TP19 "TESTPOINT" Keystone_5019 1025,2925 r180 top
TP20 "TESTPOINT" Keystone_5019 1040,1830 r180 top
TP21 "TESTPOINT" Keystone_5019 1675,2105 r180 top
TP22 "TESTPOINT" Keystone_5019 1775,1830 r180 top
TP23 "TESTPOINT" Keystone_5019 1025,2195 r180 top
TP24 "TESTPOINT" Keystone_5019 1025,2070 r180 top
"TP GND" "TESTPOINT" Keystone_5019 3245,105 r0 top
U1 "TPD1E10B06DPYR" DPY0002A 3600,2455 r90 top
U2 "TPD1E10B06DPYR" DPY0002A 3600,2720 r270 top
U3 "TPD1E10B06DPYR" DPY0002A 3725,2850 r180 top
U4 "TPD1E10B06DPYR" DPY0002A 3725,3150 r180 top
U5 "TLV4313IPWR" PW0014A_N 1420,2920 r0 top
U6 "TLV4313IPWR" PW0014A_N 1418,2066 r0 top
U7 "TPS5401DGQR" DGQ0010D_N 1145,1310 r90 top
U8 "LP2985IM5X-3.3" MF05A_N 382,583 r90 top
UART_RX_Jumper1 "M22-2510205" Harwin_M22-2510205 3700,2475 r270 top
UART_TX_Jumper1 "M22-2510205" Harwin_M22-2510205 3700,2700 r90 top
ZZ2 "These assemblies are ESD sensitive, ESD precautions shall be observed." AssemblyNote 150,3850 r0 top
ZZ3 "These assemblies must be clean and free from flux and all contaminants. Use of no clean flux is not acceptable." AssemblyNote 150,3750 r0 top
ZZ4 "These assemblies must comply with workmanship standards IPC-A-610 Class 2, unless otherwise specified." AssemblyNote 150,3650 r0 top

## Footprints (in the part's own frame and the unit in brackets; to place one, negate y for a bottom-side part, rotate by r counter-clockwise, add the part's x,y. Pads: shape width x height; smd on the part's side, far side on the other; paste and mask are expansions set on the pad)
2SN-BK-G [mil] "Samtec STEP model"
  round 1 on Mech3: 0(0,0)
  body extent -78,-39 79,39, height 188
0201 [mm] "Data from Kemet datasheet CC101_COM dated 7/28/11"
  rect 0.46x0.42 smd mask+0.048: 1(-0.33,0) 2(0.33,0)
  body extent -0.31,-0.16 0.31,0.16, height 0.26
0402 [mm] "0402 from SM-752 data"
  rect 0.8x0.6 smd: 1(-0.6,0) 2(0.6,0)
  silkscreen extent -1.22,-0.52 1.22,0.52, body extent -0.55,-0.3 0.55,0.3, height 0.6
0603 [mm] "0603 from SM-752 data"
  rect 1x0.95 smd: 1(-0.8,0) 2(0.8,0)
  silkscreen extent -1.52,-0.69 1.52,0.69, body extent -0.87,-0.47 0.87,0.47, height 1
0603_HR [mm] "0603"
  rect 0.5x0.9 smd: 1(-0.75,0) 2(0.75,0)
  silkscreen extent -1.35,-0.75 1.35,0.77, body extent -0.82,-0.47 0.82,0.47, height 0.5
0805_HV [mil] "0805 with 30mil clearance between pads"
  rect 50x63 smd: 1(-40,0) 2(40,0)
  silkscreen extent -74,-40 74,40, body extent -43,-29 43,29, height 57
1206_180 [mm] "1206_180"
  rect 1.1x1.6 smd: 1(-1.7,0) 2(1.7,0)
  silkscreen extent -0.9,-1 0.9,1, body extent -1.75,-0.95 1.75,0.95, height 1.8
1210_270 [mm] "1210"
  rect 1.3x2.7 smd: 1(-1.45,0) 2(1.45,0)
  silkscreen extent -2.32,-1.57 2.32,1.57, body extent -1.7,-1.35 1.7,1.35, height 2.7
2220_280 [mm] "Chip Capacitor, Body 5.7x5.0mm, IPC Medium Density"
  rect 1.6x5.3 smd: 1(-2.6,0) 2(2.6,0)
  silkscreen extent -3.69,-2.94 3.69,2.94, body extent -2.95,-2.62 2.95,2.62, height 2.8
AssemblyNote [mil] "Assembly Note"
Bumpon_SJ5003Transparent [mil] "3M Hemispherical Bumpon transparent"
  round 1 on Mech4: 0(0,0)
  silkscreen extent -228,-228 228,228, body extent -219,-218 219,218, height 197
CONN_SBH11-PBPC-D07-ST-BK [mm] "Sullins recommended land pattern"
  rect 1.65x1.65 hole 1.016 mask+0: 1(-7.62,-1.27)
  round 1.65 hole 1.016 mask+0: 2(-7.62,1.27) 3(-5.08,-1.27) 4(-5.08,1.27) 5(-2.54,-1.27) 6(-2.54,1.27) 7(0,-1.27) 8(0,1.27) 9(2.54,-1.27) 10(2.54,1.27) 11(5.08,-1.27) 12(5.08,1.27) 13(7.62,-1.27) 14(7.62,1.27)
  silkscreen extent -12.64,-5.08 12.64,4.7, body extent -12.64,-4.4 12.64,4.7, height 9.12
CONN_SSW-110-23-F-D [mm] "SAMTEC"
  rect 1.65x1.65 hole 1.15: 1(11.43,-1.27)
  round 1.65 hole 1.15: 2(11.43,1.27) 3(8.89,-1.27) 4(8.89,1.27) 5(6.35,-1.27) 6(6.35,1.27) 7(3.81,-1.27) 8(3.81,1.27) 9(1.27,-1.27) 10(1.27,1.27) 11(-1.27,-1.27) 12(-1.27,1.27) 13(-3.81,-1.27) 14(-3.81,1.27) 15(-6.35,-1.27) 16(-6.35,1.27) 17(-8.89,-1.27) 18(-8.89,1.27) 19(-11.43,-1.27) 20(-11.43,1.27)
  silkscreen extent -13.08,-2.46 13.08,2.54, body extent -13,-2.51 13,2.54, height 8.59
DBV0006A_N [mm] "SOT23, 6-Leads, Body 2.9x1.6mm, Pitch 0.95mm, Lead Span 2.8mm, IPC Medium Density"
  rrect17% 1x0.6 smd: 1(-1.375,0.95) 2(-1.375,0) 3(-1.375,-0.95) 4(1.375,-0.95) 5(1.375,0) 6(1.375,0.95)
  silkscreen extent -1.68,-1.55 0.5,1.55, body extent -1.42,-1.46 1.42,1.46, height 1.12
DF-S [mil] "Diodes Inc. recommended land pattern per ap02001.pdf rev 30"
  rect 88x49 smd: 1(-174.5,102.36) 2(-174.5,-102.36) 3(174.5,-102.36) 4(174.5,102.36)
  silkscreen extent -128,-168 128,180, body extent -205,-168 205,168, height 108
DGQ0010D_N [mm] "TSSOP, 10-Leads, Body 3x3mm, Pitch 0.5mm, Thermal Pad 1.88x1.57mm, IPC Medium Density"
  rrect100% 1.35x0.3 smd: 1(-2.225,1) 2(-2.225,0.5) 3(-2.225,0) 4(-2.225,-0.5) 5(-2.225,-1) 6(2.225,-1) 7(2.225,-0.5) 8(2.225,0) 9(2.225,0.5) 10(2.225,1)
  rrect6% 1.57x1.88 smd: 11(0,0)
  silkscreen extent -2.65,-1.55 0.9,1.55, body extent -2.46,-1.5 2.46,1.5, height 1.1
DPY0002A [mm] "R-PX2SON-N2"
  rect 0.6x0.5 smd: 1(-0.5,0) 2(0.5,0)
  body extent -0.55,-0.35 0.55,0.35, height 0.4
FCC_disclaimer [mil]
Fiducial10-20 [mm]
  round 1 smd mask+0.5: 1(0,0)
  Top Layer keep-out circle w1.178: c0,0 r0.5
Fischer_SL-11-112-02G [mm] "TH, 2-Leads, Body 2.5x5.08mm, Pitch 2.54mm"
  round 1.4 hole 0.9: 1(-1.27,0) 2(1.27,0)
  silkscreen extent -3.31,-1.25 2.54,1.25, body extent -2.54,-1.25 2.54,1.25, height 8.4
Fischer_SL-11-112-03G [mm] "TH, 3-Leads, Body 2.5x7.62mm, Pitch 2.54mm"
  rect 1.4x1.4 hole 0.9: 1(-2.54,0)
  round 1.4 hole 0.9: 2(0,0) 3(2.54,0)
  silkscreen extent -4.58,-1.25 3.81,1.25, body extent -3.81,-1.25 3.81,1.25, height 8.4
Harwin_M22-2510205 [mm] "Header, 2mm, 2x1, TH"
  rect 1.3x1.3 hole 0.8: 1(-1,0)
  round 1.3 hole 0.8: 2(1,0)
  silkscreen extent -2,-1.5 2,1, body extent -2,-1 2,1, height 5
Keystone_5019 [mm] "Test Point, Miniature, SMT"
  rect 3.8x2.03 smd: 1(0,0)
  silkscreen extent -2.31,-1.42 2.31,1.42, body extent -1.9,-1.02 1.9,1.02, height 2.29
LED_LTST-C170 [mm] "LITE-ON"
  rect 1.2x1.2 smd: 1(-1.05,0) 2(1.05,0)
  silkscreen extent -1.6,-1 2.2,1, body extent -1.05,-0.67 1.05,0.67, height 1.1
LED_LTST-C170_Red [mm] "LITE-ON"
  rect 1.2x1.2 smd: 1(-1.05,0) 2(1.05,0)
  silkscreen extent -1.6,-1 2.2,1, body extent -1.05,-0.67 1.05,0.67, height 1.1
LP0003A_straight [mm] "TH, 3-Leads, Pin Spacing 1.27mm"
  rrect7% 1x1 hole 0.7: 1(0,1.27)
  round 1 hole 0.7: 2(0,0) 3(0,-1.27)
  silkscreen extent -1.35,-2.41 2.65,2.95, body extent -1.34,-2.41 2.35,2.41, height 6.84
LTST-C170KFKT_Orange [mm] "LITE-ON"
  rect 1.2x1.2 smd: 1(-1.05,0) 2(1.05,0)
  silkscreen extent -1.6,-1 2.2,1, body extent -1.05,-0.67 1.05,0.67, height 1.1
LTST-C170KGKT_Green [mm] "LITE-ON"
  rect 1.2x1.2 smd: 1(-1.05,0) 2(1.05,0)
  silkscreen extent -1.6,-1 2.2,1, body extent -1.05,-0.67 1.05,0.67, height 1.1
MF05A_N [mm] "SOT23, 5-Leads, Body 2.9x1.6mm, Pitch 0.95mm, Lead Span 2.8mm, IPC Medium Density"
  rect 1.1x0.65 smd: 1(-1.2,0.95) 2(-1.2,0) 3(-1.2,-0.95) 4(1.2,-0.95) 5(1.2,0.95)
  silkscreen extent -1.32,-1.55 0.25,1.95, body extent -0.9,-1.55 0.9,1.55, height 1.19
On-Shore_ED555_8DS [mm] "Terminal Block, 3.5mm, 8-Pos, TH"
  rect 2.54x2.54 hole 1.27: 1(-12.25,0)
  round 2.54 hole 1.27: 2(-8.75,0) 3(-5.25,0) 4(-1.75,0) 5(1.75,0) 6(5.25,0) 7(8.75,0) 8(12.25,0)
  silkscreen extent -14,-3.8 14,3.1, body extent -14,-3.8 14,2.7, height 8.2
On-Shore_OSTTE020161 [mm] "Term Blk 2x1"
  rect 1.85x1.85 hole 1.2: 1(-1.75,0)
  round 1.85 hole 1.2: 2(1.75,0)
  silkscreen extent -4.47,-3.4 3.5,3.6, body extent -3.5,-3.4 3.5,3.6, height 8.4
Pb-Free_Overlay_Small [mil]
  silkscreen extent -46,-46 46,46
PW0014A_N [mm] "TSOP, 14-Leads, Body 5x4.4mm, Pitch 0.65mm, IPC Medium Density"
  oval 1.4x0.45 smd: 1(-2.95,1.95) 2(-2.95,1.3) 3(-2.95,0.65) 4(-2.95,0) 5(-2.95,-0.65) 6(-2.95,-1.3) 7(-2.95,-1.95) 8(2.95,-1.95) 9(2.95,-1.3) 10(2.95,-0.65) 11(2.95,0) 12(2.95,0.65) 13(2.95,1.3) 14(2.95,1.95)
  silkscreen extent -3.4,-2.55 1.85,2.55, body extent -3.21,-2.5 3.21,2.5, height 1
PW0020A_N [mm] "TSOP, 20-Leads, Body 6.5x4.4mm, Pitch 0.65mm, IPC Medium Density"
  oval 1.4x0.45 smd: 1(-2.95,2.925) 2(-2.95,2.275) 3(-2.95,1.625) 4(-2.95,0.975) 5(-2.95,0.325) 6(-2.95,-0.325) 7(-2.95,-0.975) 8(-2.95,-1.625) 9(-2.95,-2.275) 10(-2.95,-2.925) 11(2.95,-2.925) 12(2.95,-2.275) 13(2.95,-1.625) 14(2.95,-0.975) 15(2.95,-0.325) 16(2.95,0.325) 17(2.95,0.975) 18(2.95,1.625) 19(2.95,2.275) 20(2.95,2.925)
  silkscreen extent -3.5,-3.3 1.85,3.4, body extent -3.21,-3.25 3.21,3.25, height 1
SDR0604 [mm] "BOURNS"
  rect 2.1x5.8 smd: 1(-1.95,0) 2(1.95,0)
  body extent -2.9,-2.9 2.9,2.9, height 4.8
SM_RADIAL_B [mm] "4 x 5.8mm:  Panasonic B"
  rect 2.5x1.6 smd: 1(-1.75,0) 2(1.75,0)
  silkscreen extent -2.24,-2.25 2.25,2.25, body extent -2.25,-2.25 2.25,2.25, height 6.1
SMA [mm] "Molded Diode, 2-Leads, Body 4.3x2.6mm, IPC Medium Density, based on OnSemi component dimensions and land pattern"
  rect 2x2 smd: 1(-2,0) 2(2,0)
  silkscreen extent -3.66,-1.57 2.79,1.57, body extent -2.6,-1.3 2.6,1.3, height 2.42
SNT-100-BK-G [mil] "Samtec STEP model"
  round 1 on Mech3: 0(0,0)
  body extent -100,-50 100,50, height 344
SOD-123 [mm] "On Semi recommended land pattern"
  rect 0.915x1.22 smd: 1(-1.637,0) 2(1.637,0)
  silkscreen extent -2.74,-1.17 2.03,1.17, body extent -1.93,-0.9 1.93,0.9, height 1.35
SW_FSM4JSMA [mm] "Alcoswitch"
  rect 1.4x2.1 smd: 1(2.25,4.55) 2(2.25,-4.55) 3(-2.25,4.55) 4(-2.25,-4.55)
  silkscreen extent -3,-3 3,5.4, body extent -3,-5 3,5, height 5.1
TE_5-146278-2 [mm] "TE CONNECTIVITY"
  rect 1.65x1.65 hole 1: 1(-1.27,0)
  round 1.65 hole 1: 2(1.27,0)
  silkscreen extent -2.92,-1.27 2.54,1.27, body extent -2.41,-1.17 2.41,1.17, height 8.13
TI_Stacked_Overlay_Small [mil]
  silkscreen extent -418,-98 418,98
WL-SMCW_Blue [mm] "SMD, 2-Leads, Body 1.6x0.8mm"
  rect 0.8x0.8 smd: 1(-0.8,0) 2(0.8,0)
  silkscreen extent -1.9,-0.8 1.2,0.8, body extent -0.85,-0.45 0.85,0.45, height 0.8

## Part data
"1.65V GND" "1.65V Test" "Filter Out 1" "Filter Out 2" "LMT84 TP" "LP2985 GND" "LP2985 Out Test" "Main V+ Test" MSP_GND Reference "Set Filter" Temp TP1 TP2 TP3 TP15 TP16 TP17 TP18 TP19 TP20 TP21 TP22 TP23 TP24 "TP GND": library part 5019, "Test Point, Miniature, SMT"
C1: "CAP, CERM, 2.2 µF, 6.3 V, +/- 10%, X6S, 0402"
C2: "CAP, CERM, 1 µF, 6.3 V, +/- 10%, X5R, 0402"
C3 C4 C5 C7 C9 C12: "CAP, CERM, 0.1 µF, 16 V, +/- 5%, X7R, 0603"
C6: "CAP, AL, 10 µF, 25 V, +/- 20%, 1.35 ohm, AEC-Q200 Grade 2, SMD"
C8: "CAP, CERM, 1000 pF, 16 V, +/- 10%, X7R, 0402"
C10 C14: "CAP, CERM, 22 µF, 6.3 V, +/- 10%, X7R, 1206"
C11 C15: "CAP, CERM, 680 pF, 16 V, +/- 10%, X7R, 0201"
C13: "CAP, CERM, 0.1 µF, 10 V, +/- 10%, X5R, 0402"
C16: "CAP, CERM, 47 µF, 10 V, +/- 10%, X5R, 1206"
C17: "CAP, CERM, 2.2 µF, 100 V, +/- 10%, X7R, 1210"
C18: "CAP, CERM, 6800 pF, 50 V, +/- 10%, X7R, 0805"
C19: "CAP, CERM, 9 pF, 100 V, +/- 5%, C0G/NP0, 0805"
C20: "CAP, CERM, 0.012 µF, 6.3 V, +/- 10%, X6S, 0201"
C21: "CAP, CERM, 0.01 µF, 6.3 V, +/- 10%, X5R, 0201"
C22: "CAP, CERM, 10 µF, 100 V, +/- 20%, X7R, 2220"
D1: "Diode, Schottky, 60 V, 1 A, SMA"
D2 D3 D4 D5 D6 D7: "Diode, Ultrafast, 100 V, 0.15 A, SOD-123"
D8: "Diode, Switching-Bridge, 200 V, 1 A, DF-S"
"Dirty Coil LED1": "LED, Red, SMD"
"Dirty Filter LED1": "LED, Yellow , SMD"
"External Sensor Terminal1" "External Sensor Terminal2": "Terminal Block, 2x1, 3.5mm, TH"
FID1 FID2 FID3: "Fiducial mark.  There is nothing to buy or mount."
"Filter Bypass 1" "Filter Bypass 3": "Header, 2.54mm, 2x1, Gold, TH"
"Filter Bypass 2" "Filter Bypass 4" "Ref. VSEL1" "Supply Select 1" "Supply Select 2": "Header, 2.54mm, 3x1, Gold, TH"
"Filter Output 1" "Filter Output 2" J1 "LMT84 V+" "MSP V+" UART_RX_Jumper1 UART_TX_Jumper1: "Header, 2mm, 2x1, Gold, Black, TH"
"Filter Reset" "nRST Button": "Switch, Tactile, SPST-NO, 0.05A, 12V, SMT"
H1 H2 H3 H4: "Bumpon, Hemisphere, 0.44 X 0.20, Clear"
"I/O Block1": "Terminal Block, 3.5mm, 8-Pos, TH"
J2 J3: "Connector, Receptacle, 100mil, 10x2, Gold plated, TH"
JTAG1: "Header (shrouded), 100 mil, 7x2, Gold, TH"
L1: "Inductor, Drum Core, Ferrite, 330 µH, 0.27 A, 2.25 ohm, SMD"
LMT1: "1.5V, TO-92, Analog Temperature Sensor with Class-AB Output, LP0003A"
"Logic LED Driver": "Single 3-Input Positive-NOR Gate, DBV0006A"
Logo1: library part TI_Logo, "Texas Instrument Corporate Signature"
Logo2: library part Pb-Free
Logo3: library part FCC_disclaimer, "FCC_disclaimer"
"Low Temp LED1": "LED, Orange, SMD"
MSP1: "Mixed-Signal Microcontroller, PW0020A"
Power: "LED, Blue, SMD"
"Power Jumper1": library part 5-146278-2, "Header, 100mil, 2x1, Tin, TH"
"Power Terminal Header1": library part OSTTE020161, "Terminal Block, 2x1, 3.5mm, TH"
R1 R2 R14 R21 R30: "RES, 10.0 k, 1%, 0.063 W, 0402"
R3 R4 R5 R7 R8: "RES, 270, 5%, 0.063 W, 0402"
R6: "RES, 1.50 k, 1%, 0.063 W, 0402"
R9: "RES, 47 k, 5%, 0.063 W, 0402"
R10 R11 R13 R15 R17 R18 R20 R22: "RES, 100 k, 0.1%, 0.063 W, 0402"
R12 R19: "RES, 51.1 k, 1%, 0.063 W, 0402"
R16 R26: "RES, 200M, 5%, 0.1 W, 0603"
R24 R25: "RES, 47.0 k, 0.1%, 0.125 W, 0805"
R28: "RES, 53.6 k, 1%, 0.063 W, 0402"
R29: "RES, 105 k, 1%, 0.063 W, 0402"
R31: "RES, 71.5 k, 1%, 0.063 W, 0402"
R32: "RES, 6.49 k, 1%, 0.063 W, 0402"
R33: "RES, 402 k, 1%, 0.063 W, 0402"
SH-1 SH-2 SH-3 SH-4 SH-5 SH-6 SH-7 SH-8: "Shunt, 100mil, Gold plated, Black"
SH-9 SH-10 SH-11 SH-12 SH-13 SH-14: "Shunt, 2mm, Gold plated, Black"
"System Ok LED1": "LED, Green, SMD"
U1 U2 U3 U4: "ESD in 0402 Package with 10 pF Capacitance and 6 V Breakdown, 1 Channel, -40 to +125 degC, 2-pin X2SON (DPY), Green (RoHS & no Sb/Br)"
U5 U6: "Low-Power, Rail-to-Rail In/Out, 500-uV Typical Offset, 1-MHz Operational Amplifier for Cost-Sensitive System, PW0014A"
U7: "Buck Step Down Regulator with 3.5 to 42 V Input and 0.8 to 39 V Output, -40 to 150 degC, 10-Pin MSOP-PowerPAD (DGQ), Green (RoHS & no Sb/Br)"
U8: "Micropower 150 mA Low-Noise Ultra Low-Dropout Regulator, 5-pin SOT-23"
ZZ2 ZZ3 ZZ4: library part AssemblyNote

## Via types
v1: diameter 22, hole 10, Top Layer to Bottom Layer, tented both sides, 206 vias
v2: diameter 19.68, hole 7.87, Top Layer to Bottom Layer, 5 vias
v3: diameter 36, hole 16, Top Layer to Bottom Layer, tented both sides, 1 vias

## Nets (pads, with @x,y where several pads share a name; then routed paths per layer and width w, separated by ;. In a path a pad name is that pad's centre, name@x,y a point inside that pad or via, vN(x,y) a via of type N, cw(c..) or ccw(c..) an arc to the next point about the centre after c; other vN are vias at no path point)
1.65V: "1.65V Test.1" "Ref. VSEL1.3" "Supply Select 1.3" "Supply Select 2.3" C3.2 R1.1 R2.1 U5.3 U5.5 U5.10 U6.3 U6.5 U6.10 | length 5613.1
  Top Layer w10: U6.5@1301.86,2040.41 U6.10@1534.14,2040.41 ; U6.3@1301.86,2091.59 v1(1350,2091.59) 1403.41,2091.59 1420,2075 1420,2040.41 ; U5.5@1301.86,2895.41 U5.10@1534.14,2895.41 ; U5.3@1301.86,2946.59 v1(1352.63,2946.59) 1403.41,2946.59 1420,2930 1420,2895.41
  Top Layer w20: 250,1140 220,1140 150,1210 150,1275 198.62,1323.62 R2.1@375,1323.62 ; R1.1@375,1376.38 R2.1@375,1323.62 ; C3.2@450,1323.62 v1(410,1323.62) R2.1@375,1323.62
  Signal Layer 2 w10: 1300,2395 1300,2141.59 v1(1350,2091.59) ; 1300,3275 1300,2999.22 v1(1352.63,2946.59)
  Signal Layer 2 w20: v1(410,1323.62) 410,2935 655,3180 1150,3180 1245,3275 1300,3275 ; 410,2260 980,2260 1115,2395 1300,2395
5VDC_P: "Main V+ Test.1" "Power Jumper1.1" C16.1 J1.1 L1.2 R28.2 | length 2687.2
  Top Layer w10: J1.1@425,165.63 J1.1@430.63,160 ; L1.2@753.23,1485 L1.2@763.07,1475.16 ; v1(1150,1655) R28.2@1181.38,1655
  Top Layer w40: 135,375 425,375 ; J1.1@425,165.63 425,375 ; L1.2@763.07,1475.16 C16.1@763.07,1315 v1(725,1315) 680,1315 645,1280 645,662 425,442 425,375
  Signal Layer 2 w10: v1(725,1315) 700,1315 670,1345 670,1635 690,1655 v1(1150,1655)
CC2650_VDD: "Filter Reset.3" "Filter Reset.4" "LMT84 TP.1" "LMT84 V+.2" "Logic LED Driver.5" "LP2985 Out Test.1" "MSP V+.2" "Ref. VSEL1.1" C1.1 C4.2 C6.1 C7.2 C9.2 C12.2 J3.2 JTAG1.4 Power.2 R1.2 R9.2 U5.4 U6.4 U8.5 | length 16067
  Top Layer w8: C1.1@333,680.05 337.95,685 C1.1@340,687.05
  Top Layer w15: v1(1170,2051.5) C12.2@1210,2051.5 1224.5,2066 U6.4@1301.86,2066 ; v1(1170,2906.5) C9.2@1210,2906.5 1224.5,2921 U5.4@1301.86,2921 ; 2440,3269.37 2440,3005 2520.87,2924.13 2520.87,2813.58 2879.13,2813.58 ; Power.2@3100,2088.5 3247.13,2088.5 ; R9.2@3123.62,1850 C6.1@3226.1,1850 C6.1@3231.1,1850
  Top Layer w20: 140,815 140,745 200,685 C1.1@337.95,685 ; 150,1475 265,1475 316.38,1423.62 R1.2@375,1423.62 ; 2280.63,3269.37 2440,3269.37 2520,3269.37 2590.63,3340 C4.2@2658.5,3340
  Top Layer w25: C1.1@340,687.05 344.6,682.45 U8.5@344.6,630.24
  Top Layer w30: C1.1@340,687.05 v3(340,745) ; v1(3235,1795) 3235,1846.1 3231.1,1850 C6.1@3243.5,1862.4 ; 3247.13,2088.5 3250,2085.63 C6.1@3250,1865
  Signal Layer 2 w15: 2520,3269.37 4035.63,3269.37 4115,3190 4115,3115 JTAG1.4@4050,3050
  Signal Layer 2 w20: 150,1475 105,1475 70,1440 70,960 285,745 v3(340,745) ; v1(1170,2906.5) 1321.5,2755 1575,2755 2089.37,3269.37 2520,3269.37 ; J3.2@1500,1300 1575,1375 2230,1375 2480,1125 v1(2480,1045)
  Signal Layer 2 w30: v3(340,745) 340,940 410,1010 410,1180 545,1315 545,1595 705,1755 3195,1755 v1(3235,1795)
  Signal Layer 2 w40: v3(340,745) 390,745 695,1050 1250,1050 J3.2@1500,1300
  Bottom Layer w40: v3@340,760 340,1530 565,1755 873.5,1755 v1(1170,2051.5) v1(1170,2906.5)
DIO8_MISO: "I/O Block1.6" J2.13 MSP1.8 | length 2726.1
  Top Layer w12: J2.13@3290,700 J2.13@3300,700 3670,1070 3670,1840 3323.98,2186.02 MSP1.8@3323.98,2283.86
  Bottom Layer w15: J2.13@3300,700 3465,700 3671.69,906.69 4050,906.69
DIO9_MOSI: "I/O Block1.7" J2.11 MSP1.7 | length 2465
  Top Layer w12: MSP1.7@3298.39,2283.86 3298.39,2318.39 3325,2345 3380,2345 3830,1895 v1(3830,1045)
  Bottom Layer w15: J2.11@3300,800 3450,800 3695,1045 4050,1045
DIO13_BTN1: "I/O Block1.5" J2.15 MSP1.9 | length 2818.8
  Top Layer w12: J2.15@3300,600 3705,1005 3705,1860 3349.57,2215.43 MSP1.9@3349.57,2283.86
  Bottom Layer w15: J2.15@3300,600 3485,600 3653.9,768.9 4050,768.9
DIO23_ANALOG: "Dirty Filter LED1.1" "I/O Block1.1" "Logic LED Driver.6" J3.4 MSP1.10 | length 5673.2
  Top Layer w10: MSP1.10@3375.16,2283.86 3375.16,2239.84 3740,1875 3740,520 4040,220 4060,220
  Top Layer w20: 2454.13,1082.4 v1(2412.4,1082.4) 2400,1070 2400,640 2465,575 v1(2495,575) 2533.66,575
  Signal Layer 2 w10: J3.4@1500,1200 1550,1150 2344.8,1150 v1(2412.4,1082.4) ; v1(2495,575) 2852.28,217.72 4050,217.72
DIO24_ANALOG: "Dirty Coil LED1.1" "I/O Block1.2" "Logic LED Driver.3" J3.12 MSP1.11 | length 6166.2
  Top Layer w12: MSP1.11@3375.16,2516.14 3393.86,2516.14 4165,1745 4165,470.51 4050,355.51
  Top Layer w20: 2033.66,575 2033.66,668.66 2090,725 v1(2230,725) 2345.87,840.87 2345.87,1007.6
  Signal Layer 2 w10: J3.12@1500,800 1550,850 2125,850 2255,980 v1(2345,980) ; v1(2230,725) 2415,725 2885,255 3949.49,255 4050,355.51
DIO25_ANALOG: "I/O Block1.4" J3.5 MSP1.12 | length 5139.2
  Top Layer w12: MSP1.12@3349.57,2516.14 3349.57,2485.43 4135,1700 4135,716.1 4050,631.1
  Signal Layer 2 w10: J3.5@1600,1100 2320,1100 3090,330 3655,330 3956.1,631.1 4050,631.1
DIO26_ANALOG: "I/O Block1.3" "Logic LED Driver.1" "Low Temp LED1.1" J3.7 MSP1.13 | length 5834.7
  Top Layer w12: MSP1.13@3323.98,2516.14 3323.98,2471.02 4110,1685 4110,860 4090,840 4000,840 3955,795 3955,585 4050,490
  Top Layer w20: 2033.66,850 2033.66,918.66 v1(2180,1065) 2197.4,1082.4 2345.87,1082.4
  Signal Layer 2 w10: J3.7@1600,1000 2115,1000 v1(2180,1065) 2300,1065 3070,295 3760,295 3958.31,493.31 4050,493.31
FILTER_OUT_1: "Filter Bypass 2.1" "Filter Out 1.1" "Filter Output 1.2" MSP1.19 | length 2860.5
  Top Layer w10: 2089.37,2835 2275,2835
  Top Layer w15: 2275,2825 2275,2700 2405,2570 3155,2570 3170.43,2554.57 MSP1.19@3170.43,2516.14
  Signal Layer 2 w10: 575,2725 1989.37,2725 2089.37,2825
FILTER_OUT_2: "Filter Bypass 4.1" "Filter Out 2.1" "Filter Output 2.2" MSP1.18 | length 3105.5
  Top Layer w10: 2089.37,1980 2275,1980
  Top Layer w15: 2275,1980 2275,2305 2415,2445 3170,2445 3196.02,2471.02 MSP1.18@3196.02,2516.14
  Signal Layer 2 w10: 575,1870 1979.37,1870 2089.37,1980
FILTER_SENS_IN1: "Filter Bypass 2.3" R14.1 | length 276.4
  Top Layer w20: 575,2925 R14.1@851.38,2925
FILTER_SENS_IN2: "Filter Bypass 4.3" R21.2 | length 276.4
  Top Layer w20: 575,2070 R21.2@851.38,2070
